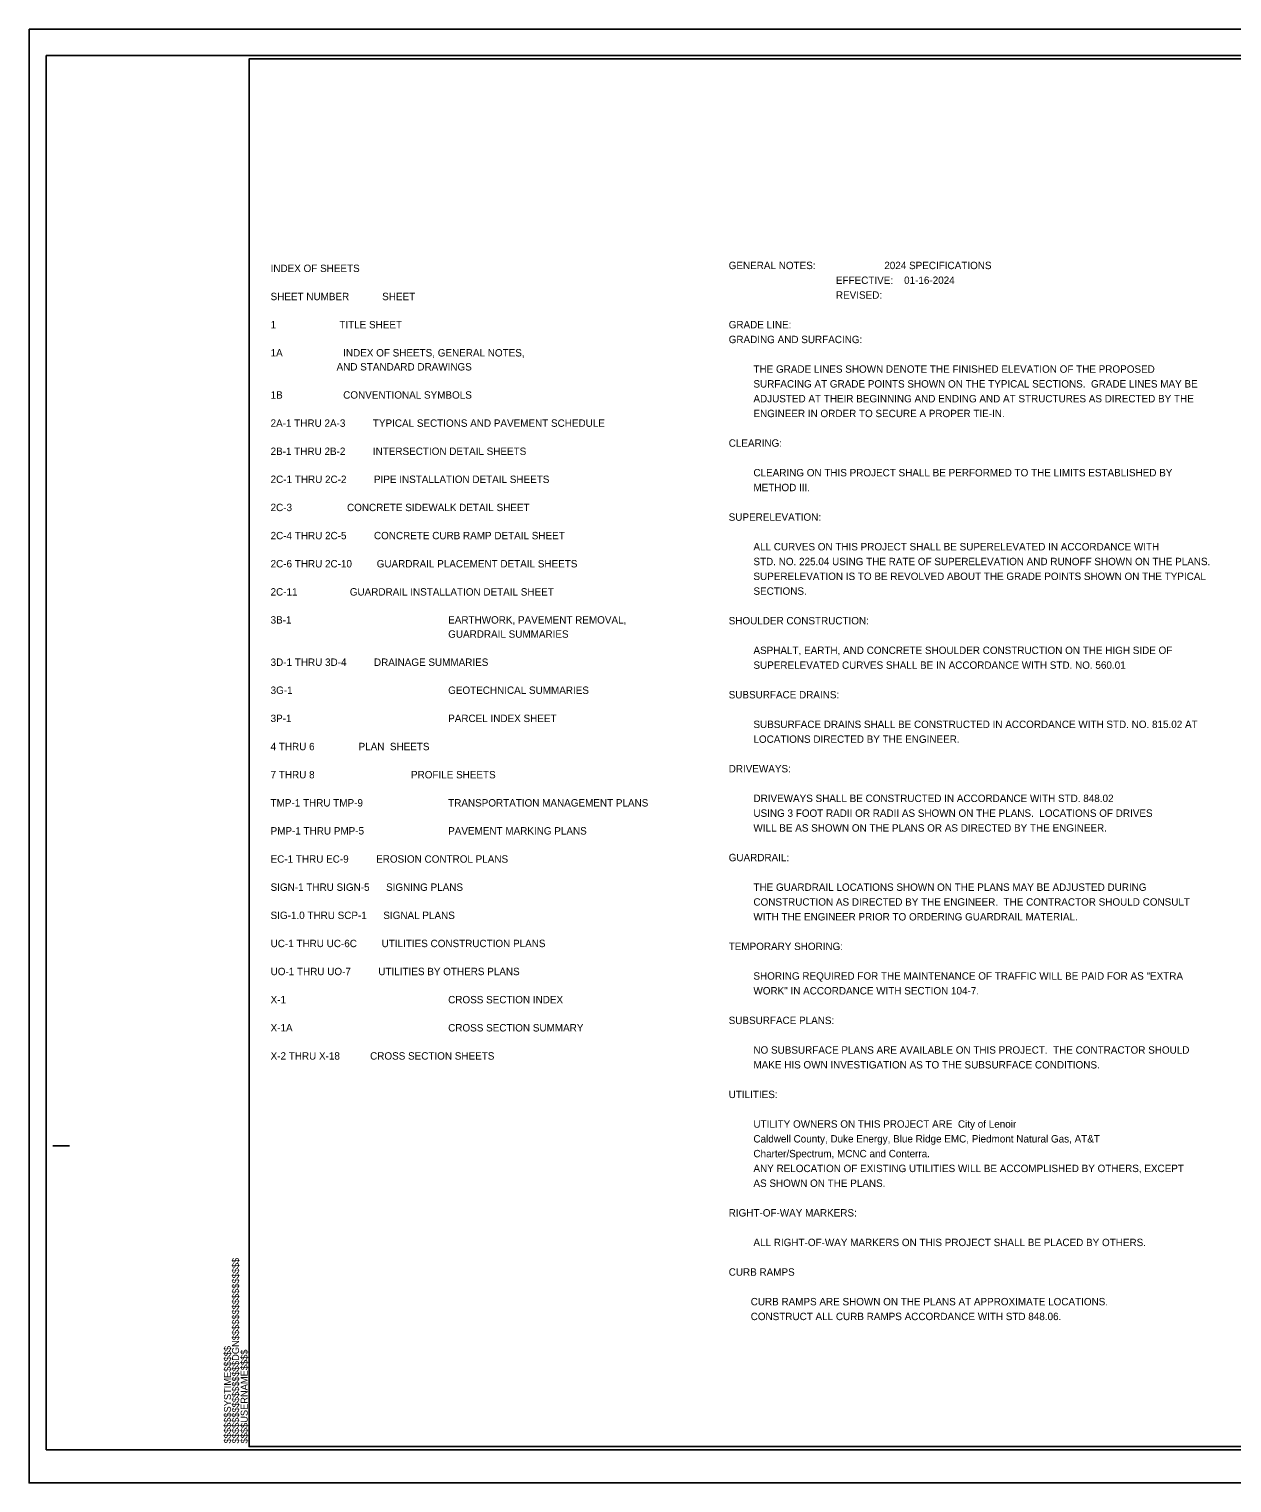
# Model space of a CAD drawing. Extents: x 573687 to 575387, y -53365 to -52265.
# Drawn here: x 573687 to 574597, y -53365 to -52265 of the extents above; entities that cross this region are included whole.
import ezdxf

# ---------------------------------------------------------------- set-up
doc = ezdxf.new("R2010")
doc.units = 0
for name, color, linetype in [('Sheet Cutting Line CELL', 7, 'Continuous'), ('Sheet Data Text CELL', 7, 'Continuous'), ('Sheet Plan CELL', 7, 'Continuous'), ('Sheet Plot Border Inside CELL', 7, 'Continuous'), ('Sheet Plot Border Outside CELL', 7, 'Continuous')]:
    doc.layers.add(name, color=color, linetype=linetype)

msp = doc.modelspace()

# ---------------------------------------------------------------- linework, layer by layer
at = {"layer": 'Sheet Cutting Line CELL'}
msp.add_line((575370.2, -52264.9), (573686.7, -52264.9), dxfattribs=at)
at = {"layer": 'Sheet Plan CELL'}
for p, q in [((573704.7, -53109.9), (573717.2, -53109.9)), ((573853.2, -53337.4), (573853.2, -53337.4))]:
    msp.add_line(p, q, dxfattribs=at)
msp.add_lwpolyline([(575353.2, -52287.4), (573853.2, -52287.4), (573853.2, -53337.4), (575353.2, -53337.4)], close=True, dxfattribs=at)
at = {"layer": 'Sheet Plot Border Inside CELL'}
msp.add_lwpolyline([(573699.7, -53339.9), (575365.7, -53339.9), (575365.7, -52284.9), (573699.7, -52284.9)], close=True, dxfattribs=at)
at = {"layer": 'Sheet Plot Border Outside CELL'}
msp.add_lwpolyline([(573686.7, -52264.9), (575386.7, -52264.9), (575386.7, -53364.9), (573686.7, -53364.9)], close=True, dxfattribs=at)

# ---------------------------------------------------------------- texts
at = {"layer": 'Sheet Data Text CELL'}
for s, p in [('INDEX OF SHEETS ', (573869.5, -52448.7)), ('SHEET NUMBER            SHEET   ', (573869.5, -52470)), ('1                       TITLE SHEET', (573869.5, -52491.3)), ('1A                      INDEX OF SHEETS, GENERAL NOTES, ', (573869.5, -52512.6)), ('                        AND STANDARD DRAWINGS', (573869.5, -52523.2)), ('1B                      CONVENTIONAL SYMBOLS', (573869.5, -52544.5)), ('2A-1 THRU 2A-3          TYPICAL SECTIONS AND PAVEMENT SCHEDULE', (573869.5, -52565.8)), ('2B-1 THRU 2B-2          INTERSECTION DETAIL SHEETS', (573869.5, -52587.1)), ('2C-1 THRU 2C-2          PIPE INSTALLATION DETAIL SHEETS', (573869.5, -52608.3)), ('2C-3                    CONCRETE SIDEWALK DETAIL SHEET', (573869.5, -52629.6)), ('2C-4 THRU 2C-5          CONCRETE CURB RAMP DETAIL SHEET ', (573869.5, -52650.9)), ('2C-6 THRU 2C-10         GUARDRAIL PLACEMENT DETAIL SHEETS', (573869.5, -52672.2)), ('2C-11                   GUARDRAIL INSTALLATION DETAIL SHEET                  ', (573869.5, -52693.5)), ('3B-1', (573869.5, -52714.7)), ('EARTHWORK, PAVEMENT REMOVAL,', (574003.9, -52714.7)), ('GUARDRAIL SUMMARIES', (574003.9, -52725.4)), ('3D-1 THRU 3D-4          DRAINAGE SUMMARIES ', (573869.5, -52746.7)), ('3G-1', (573869.5, -52767.9)), ('GEOTECHNICAL SUMMARIES ', (574003.9, -52767.9)), ('3P-1', (573869.5, -52789.2)), ('PARCEL INDEX SHEET', (574003.9, -52789.2)), ('4 THRU 6                PLAN  SHEETS', (573869.5, -52810.5)), ('7 THRU 8      ', (573869.5, -52831.8)), ('        PROFILE SHEETS', (573959.1, -52831.8)), ('TMP-1 THRU TMP-9', (573869.5, -52853.1)), ('TRANSPORTATION MANAGEMENT PLANS', (574003.9, -52853.1)), ('PMP-1 THRU PMP-5', (573869.5, -52874.3)), ('PAVEMENT MARKING PLANS', (574003.9, -52874.3)), ('EC-1 THRU EC-9          EROSION CONTROL PLANS', (573869.5, -52895.6)), ('SIGN-1 THRU SIGN-5      SIGNING PLANS', (573869.5, -52916.9)), ('SIG-1.0 THRU SCP-1      SIGNAL PLANS', (573869.5, -52938.2)), ('UC-1 THRU UC-6C         UTILITIES CONSTRUCTION PLANS', (573869.5, -52959.5)), ('UO-1 THRU UO-7          UTILITIES BY OTHERS PLANS', (573869.5, -52980.7)), ('X-1                    ', (573869.5, -53002)), ('CROSS SECTION INDEX', (574003.9, -53002)), ('X-1A', (573869.5, -53023.3)), ('CROSS SECTION SUMMARY', (574003.9, -53023.3)), ('X-2 THRU X-18           CROSS SECTION SHEETS', (573869.5, -53044.6))]:
    msp.add_text(s, height=5.6, rotation=360, dxfattribs=at).set_placement(p)
for s, p in [('GENERAL NOTES:                         2024 SPECIFICATIONS', (574216.2, -52446.5)), ('                                       EFFECTIVE:    01-16-2024', (574216.2, -52457.7)), ('                                       REVISED:      ', (574216.2, -52468.9)), ('GRADE LINE:  ', (574216.2, -52491.3)), ('GRADING AND SURFACING:  ', (574216.2, -52502.5)), ('         THE GRADE LINES SHOWN DENOTE THE FINISHED ELEVATION OF THE PROPOSED ', (574216.2, -52524.9)), ('         SURFACING AT GRADE POINTS SHOWN ON THE TYPICAL SECTIONS.  GRADE LINES MAY BE ', (574216.2, -52536.1)), ('         ADJUSTED AT THEIR BEGINNING AND ENDING AND AT STRUCTURES AS DIRECTED BY THE ', (574216.2, -52547.3)), ('         ENGINEER IN ORDER TO SECURE A PROPER TIE-IN.  ', (574216.2, -52558.5)), ('CLEARING:  ', (574216.2, -52580.9)), ('         CLEARING ON THIS PROJECT SHALL BE PERFORMED TO THE LIMITS ESTABLISHED BY ', (574216.2, -52603.3)), ('         METHOD III.', (574216.2, -52614.5)), ('SUPERELEVATION:  ', (574216.2, -52636.9)), ('         ALL CURVES ON THIS PROJECT SHALL BE SUPERELEVATED IN ACCORDANCE WITH', (574216.2, -52659.3)), ('         STD. NO. 225.04 USING THE RATE OF SUPERELEVATION AND RUNOFF SHOWN ON THE PLANS.', (574216.2, -52670.5)), ('         SUPERELEVATION IS TO BE REVOLVED ABOUT THE GRADE POINTS SHOWN ON THE TYPICAL ', (574216.2, -52681.7)), ('         SECTIONS.  ', (574216.2, -52692.9)), ('SHOULDER CONSTRUCTION:  ', (574216.2, -52715.3)), ('         ASPHALT, EARTH, AND CONCRETE SHOULDER CONSTRUCTION ON THE HIGH SIDE OF', (574216.2, -52737.7)), ('         SUPERELEVATED CURVES SHALL BE IN ACCORDANCE WITH STD. NO. 560.01', (574216.2, -52748.9)), ('SUBSURFACE DRAINS:', (574216.2, -52771.3)), ('         SUBSURFACE DRAINS SHALL BE CONSTRUCTED IN ACCORDANCE WITH STD. NO. 815.02 AT ', (574216.2, -52793.7)), ('         LOCATIONS DIRECTED BY THE ENGINEER.  ', (574216.2, -52804.9)), ('DRIVEWAYS:  ', (574216.2, -52827.3)), ('         DRIVEWAYS SHALL BE CONSTRUCTED IN ACCORDANCE WITH STD. 848.02', (574216.2, -52849.7)), ('         USING 3 FOOT RADII OR RADII AS SHOWN ON THE PLANS.  LOCATIONS OF DRIVES', (574216.2, -52860.9)), ('         WILL BE AS SHOWN ON THE PLANS OR AS DIRECTED BY THE ENGINEER.  ', (574216.2, -52872.1)), ('GUARDRAIL:  ', (574216.2, -52894.5)), ('         THE GUARDRAIL LOCATIONS SHOWN ON THE PLANS MAY BE ADJUSTED DURING ', (574216.2, -52916.9)), ('         CONSTRUCTION AS DIRECTED BY THE ENGINEER.  THE CONTRACTOR SHOULD CONSULT', (574216.2, -52928.1)), ('         WITH THE ENGINEER PRIOR TO ORDERING GUARDRAIL MATERIAL.', (574216.2, -52939.3)), ('TEMPORARY SHORING:  ', (574216.2, -52961.7)), ('         SHORING REQUIRED FOR THE MAINTENANCE OF TRAFFIC WILL BE PAID FOR AS "EXTRA ', (574216.2, -52984.1)), ('         WORK" IN ACCORDANCE WITH SECTION 104-7.  ', (574216.2, -52995.3)), ('SUBSURFACE PLANS:  ', (574216.2, -53017.7)), ('         NO SUBSURFACE PLANS ARE AVAILABLE ON THIS PROJECT.  THE CONTRACTOR SHOULD ', (574216.2, -53040.1)), ('         MAKE HIS OWN INVESTIGATION AS TO THE SUBSURFACE CONDITIONS.  ', (574216.2, -53051.3)), ('UTILITIES:  ', (574216.2, -53073.7)), ('         UTILITY OWNERS ON THIS PROJECT ARE  City of Lenoir', (574216.2, -53096.1)), ('         Caldwell County, Duke Energy, Blue Ridge EMC, Piedmont Natural Gas, AT&T', (574216.2, -53107.3)), ('         Charter/Spectrum, MCNC and Conterra.', (574216.2, -53118.5)), ('         ANY RELOCATION OF EXISTING UTILITIES WILL BE ACCOMPLISHED BY OTHERS, EXCEPT ', (574216.2, -53129.7)), ('         AS SHOWN ON THE PLANS.  ', (574216.2, -53140.9)), ('RIGHT-OF-WAY MARKERS:  ', (574216.2, -53163.3)), ('         ALL RIGHT-OF-WAY MARKERS ON THIS PROJECT SHALL BE PLACED BY OTHERS.  ', (574216.2, -53185.7)), ('CURB RAMPS', (574216.2, -53208.1)), ('        CURB RAMPS ARE SHOWN ON THE PLANS AT APPROXIMATE LOCATIONS.', (574216.2, -53230.5)), ('        CONSTRUCT ALL CURB RAMPS ACCORDANCE WITH STD 848.06.', (574216.2, -53241.7))]:
    msp.add_text(s, height=5.6, dxfattribs=at).set_placement(p)
at = {"layer": 'Sheet Plan CELL'}
for s, p in [('$$$$$$$$$$$$$$$$DGN$$$$$$$$$$$$$$$$', (573845.6, -53335)), ('$$$$$$SYSTIME$$$$$', (573839.5, -53335)), ('$$$$USERNAME$$$$', (573852.1, -53335))]:
    msp.add_text(s, height=5.25, rotation=90, dxfattribs=at).set_placement(p)

doc.saveas('drawing.dxf')
